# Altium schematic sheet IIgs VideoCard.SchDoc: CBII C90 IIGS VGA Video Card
size A2; Engineer: srkh; DocumentNumber: 1; Revision: c90; SheetNumber: 1; SheetTotal: 1
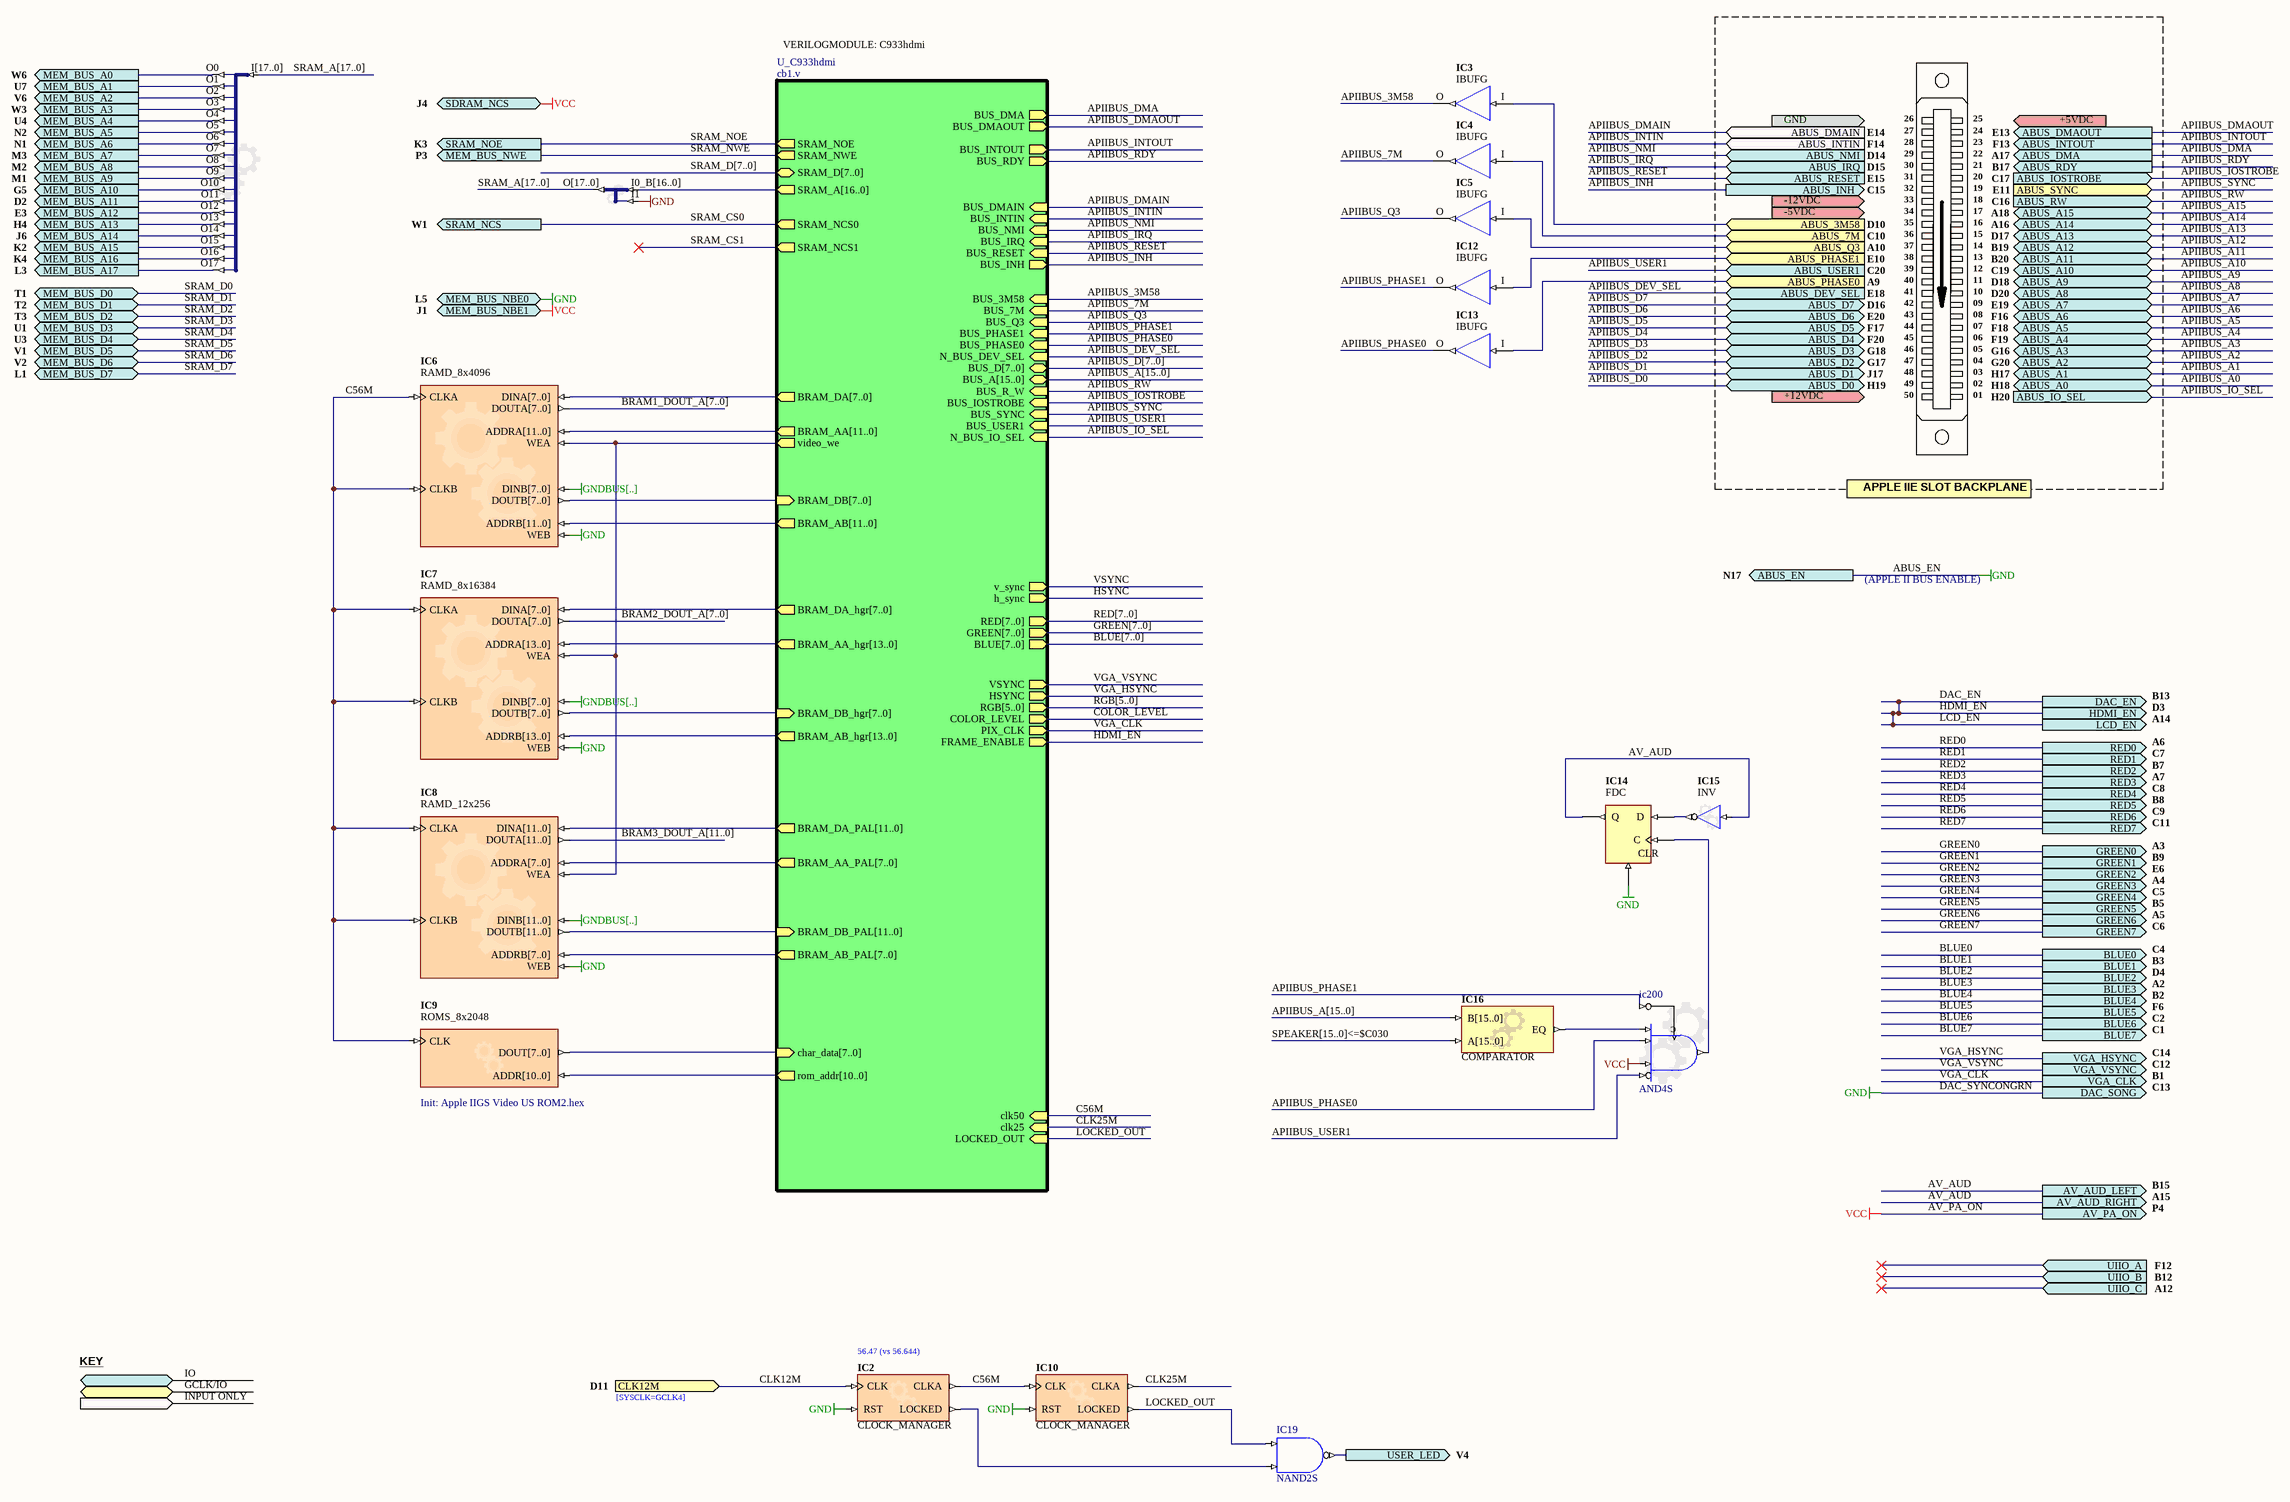
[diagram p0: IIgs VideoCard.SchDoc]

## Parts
IC2  CLOCK_MANAGER
IC3  IBUFG
IC4  IBUFG
IC5  IBUFG
IC6  RAMD_8x4096
IC7  RAMD_8x16384
IC8  RAMD_12x256
IC9  ROMS_8x2048
IC10  CLOCK_MANAGER
IC11  BUS_JS  (value not drawn)
IC12  IBUFG
IC13  IBUFG
IC14  FDC
IC15  INV
IC16  COMPARATOR
IC19  NAND2S
ic200  AND4S
U3001  BUS_JS  (value not drawn)

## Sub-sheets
U_C933hdmi = cb1.v: BLUE[7..0] (out), BUS_3M58 (in), BUS_7M (in), BUS_A[15..0] (bidir), BUS_D[7..0] (bidir), BUS_DMA (out), BUS_DMAIN (in), BUS_DMAOUT (out), BUS_INH (out), BUS_INTIN (in), BUS_INTOUT (out), BUS_IOSTROBE (in), BUS_IRQ (in), BUS_NMI (in), BUS_PHASE0 (in), BUS_PHASE1 (in), BUS_Q3 (in), BUS_R_W (in), BUS_RDY (out), BUS_RESET (in), BUS_SYNC (in), BUS_USER1 (in), COLOR_LEVEL (out), FRAME_ENABLE (out), GREEN[7..0] (out), h_sync (out), HSYNC (out), N_BUS_DEV_SEL (in), N_BUS_IO_SEL (in), PIX_CLK (out), RED[7..0] (out), RGB[5..0] (out), SRAM_A[16..0] (out), SRAM_D[7..0] (bidir), SRAM_NCS0 (out), SRAM_NCS1 (out), SRAM_NOE (out), SRAM_NWE (out), v_sync (out), VSYNC (out), clk25 (in), clk50 (in), LOCKED_OUT (in), rom_addr[10..0] (out), char_data[7..0] (in), BRAM_AA_PAL[7..0] (out), BRAM_DA_PAL[11..0] (out), BRAM_AB_PAL[7..0] (out), BRAM_DB_PAL[11..0] (in), BRAM_AA[11..0] (out), BRAM_DA[7..0] (out), video_we (out), BRAM_AB[11..0] (out), BRAM_DB[7..0] (in), BRAM_AA_hgr[13..0] (out), BRAM_DA_hgr[7..0] (out), BRAM_AB_hgr[13..0] (out), BRAM_DB_hgr[7..0] (in)  | VERILOGMODULE: C933hdmi

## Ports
ABUS_3M58 (in, see D10), ABUS_7M (in, see C10), ABUS_A0 (bidir, see H18), ABUS_A1 (bidir, see H17), ABUS_A2 (bidir, see G20), ABUS_A3 (bidir, see G16), ABUS_A4 (bidir, see F19), ABUS_A5 (bidir, see F18), ABUS_A6 (bidir, see F16), ABUS_A7 (bidir, see E19), ABUS_A8 (bidir, see D20), ABUS_A9 (bidir, see D18), ABUS_A10 (bidir, see C19), ABUS_A11 (bidir, see B20), ABUS_A12 (bidir, see B19), ABUS_A13 (bidir, see D17), ABUS_A14 (bidir, see A16), ABUS_A15 (bidir, see A18), ABUS_D0 (bidir, see H19), ABUS_D1 (bidir, see J17), ABUS_D2 (bidir, see G17), ABUS_D3 (bidir, see G18), ABUS_D4 (bidir, see F20), ABUS_D5 (bidir, see F17), ABUS_D6 (bidir, see E20), ABUS_D7 (bidir, see D16), ABUS_DEV_SEL (in, see E18), ABUS_DMA (out, see A17), ABUS_DMAIN (in, see E14), ABUS_DMAOUT (out, see E13), ABUS_EN (out, see N17), ABUS_INH (out, see C15), ABUS_INTIN (in, see F14), ABUS_INTOUT (out, see F13), ABUS_IO_SEL (in, see H20), ABUS_IOSTROBE (in, see C17), ABUS_IRQ (in, see D15), ABUS_NMI (in, see D14), ABUS_PHASE0 (in, see A9), ABUS_PHASE1 (in, see E10), ABUS_Q3 (in, see A10), ABUS_RDY (out, see B17), ABUS_RESET (in, see E15), ABUS_RW (in, see C16), ABUS_SYNC (in, see E11), ABUS_USER1 (in, see C20), AV_AUD_LEFT (out, see B15), AV_AUD_RIGHT (out, see A15), AV_PA_ON (out, see P4), BLUE0 (out, see C4), BLUE1 (out, see B3), BLUE2 (out, see D4), BLUE3 (out, see A2), BLUE4 (out, see B2), BLUE5 (out, see F6), BLUE6 (out, see C2), BLUE7 (out, see C1), CLK12M (in, see D11), DAC_EN (out, see B13), DAC_SONG (out, see C13), GREEN0 (out, see A3), GREEN1 (out, see B9), GREEN2 (out, see E6), GREEN3 (out, see A4), GREEN4 (out, see C5), GREEN5 (out, see B5), GREEN6 (out, see A5), GREEN7 (out, see C6), HDMI_EN (out, see D3), LCD_EN (out, see A14), MEM_BUS_A0 (out, see W6), MEM_BUS_A1 (out, see U7), MEM_BUS_A2 (out, see V6), MEM_BUS_A3 (out, see W3), MEM_BUS_A4 (out, see U4), MEM_BUS_A5 (out, see N2), MEM_BUS_A6 (out, see N1), MEM_BUS_A7 (out, see M3), MEM_BUS_A8 (out, see M2), MEM_BUS_A9 (out, see M1), MEM_BUS_A10 (out, see G5), MEM_BUS_A11 (out, see D2), MEM_BUS_A12 (out, see E3), MEM_BUS_A13 (out, see H4), MEM_BUS_A14 (out, see J6), MEM_BUS_A15 (out, see K2), MEM_BUS_A16 (out, see K4), MEM_BUS_A17 (out, see L3), MEM_BUS_D0 (bidir, see T1), MEM_BUS_D1 (bidir, see T2), MEM_BUS_D2 (bidir, see T3), MEM_BUS_D3 (bidir, see U1), MEM_BUS_D4 (bidir, see U3), MEM_BUS_D5 (bidir, see V1), MEM_BUS_D6 (bidir, see V2), MEM_BUS_D7 (bidir, see L1), MEM_BUS_NBE0 (out, see L5), MEM_BUS_NBE1 (out, see J1), MEM_BUS_NWE (out, see P3), RED0 (out, see A6), RED1 (out, see C7), RED2 (out, see B7), RED3 (out, see A7), RED4 (out, see C8), RED5 (out, see B8), RED6 (out, see C9), RED7 (out, see C11), SDRAM_NCS (out, see J4), SRAM_NCS (out, see W1), SRAM_NOE (out, see K3), UIIO_A (in, see F12), UIIO_B (in, see B12), UIIO_C (in, see A12), USER_LED (out, see V4), VGA_CLK (out, see B1), VGA_HSYNC (out, see C14), VGA_VSYNC (out, see C12)

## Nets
ABUS_EN: IC2.RST IC6.WEB IC7.WEB IC8.WEB IC10.RST IC14.CLR U3001.I1 ; port ABUS_EN, port DAC_SONG, port MEM_BUS_NBE0  [also labelled DAC_SYNCONGRN, GND]
AV_PA_ON: ic200.I1 ; port AV_PA_ON, port MEM_BUS_NBE1, port SDRAM_NCS  [also labelled VCC]
GNDBUS[..]: IC6.DINB[7..0] IC7.DINB[7..0] IC8.DINB[11..0]
ABUS_3M58: IC3.I ; port ABUS_3M58
ABUS_7M: IC4.I ; port ABUS_7M
ABUS_PHASE0: IC13.I ; port ABUS_PHASE0
ABUS_PHASE1: IC12.I ; port ABUS_PHASE1
ABUS_Q3: IC5.I ; port ABUS_Q3
APIIBUS_3M58: IC3.O ; sheet U_C933hdmi/BUS_3M58
APIIBUS_7M: IC4.O ; sheet U_C933hdmi/BUS_7M
APIIBUS_DEV_SEL: port ABUS_DEV_SEL, sheet U_C933hdmi/N_BUS_DEV_SEL
APIIBUS_DMA: port ABUS_DMA, sheet U_C933hdmi/BUS_DMA
APIIBUS_DMAIN: port ABUS_DMAIN, sheet U_C933hdmi/BUS_DMAIN
APIIBUS_DMAOUT: port ABUS_DMAOUT, sheet U_C933hdmi/BUS_DMAOUT
APIIBUS_INH: port ABUS_INH, sheet U_C933hdmi/BUS_INH
APIIBUS_INTIN: port ABUS_INTIN, sheet U_C933hdmi/BUS_INTIN
APIIBUS_INTOUT: port ABUS_INTOUT, sheet U_C933hdmi/BUS_INTOUT
APIIBUS_IO_SEL: port ABUS_IO_SEL, sheet U_C933hdmi/N_BUS_IO_SEL
APIIBUS_IOSTROBE: port ABUS_IOSTROBE, sheet U_C933hdmi/BUS_IOSTROBE
APIIBUS_IRQ: port ABUS_IRQ, sheet U_C933hdmi/BUS_IRQ
APIIBUS_NMI: port ABUS_NMI, sheet U_C933hdmi/BUS_NMI
APIIBUS_PHASE0: IC13.O ic200.I2 ; sheet U_C933hdmi/BUS_PHASE0
APIIBUS_PHASE1: IC12.O ic200.C ; sheet U_C933hdmi/BUS_PHASE1
APIIBUS_Q3: IC5.O ; sheet U_C933hdmi/BUS_Q3
APIIBUS_RDY: port ABUS_RDY, sheet U_C933hdmi/BUS_RDY
APIIBUS_RESET: port ABUS_RESET, sheet U_C933hdmi/BUS_RESET
APIIBUS_RW: port ABUS_RW, sheet U_C933hdmi/BUS_R_W
APIIBUS_SYNC: port ABUS_SYNC, sheet U_C933hdmi/BUS_SYNC
APIIBUS_USER1: ic200.I0 ; port ABUS_USER1, sheet U_C933hdmi/BUS_USER1
AV_AUD: IC14.Q IC15.I ; port AV_AUD_LEFT, port AV_AUD_RIGHT
C56M: IC2.CLKA IC6.CLKA IC6.CLKB IC7.CLKA IC7.CLKB IC8.CLKA IC8.CLKB IC9.CLK IC10.CLK ; sheet U_C933hdmi/clk50
CLK12M: IC2.CLK ; port CLK12M
CLK25M: IC10.CLKA ; sheet U_C933hdmi/clk25
DAC_EN: port HDMI_EN, port DAC_EN, port LCD_EN, sheet U_C933hdmi/FRAME_ENABLE  [also labelled HDMI_EN, LCD_EN]
LOCKED_OUT: IC10.LOCKED IC19.I1 ; sheet U_C933hdmi/LOCKED_OUT
MEM_BUS_A0: IC11.O0 ; port MEM_BUS_A0
MEM_BUS_A1: IC11.O1 ; port MEM_BUS_A1
MEM_BUS_A2: IC11.O2 ; port MEM_BUS_A2
MEM_BUS_A3: IC11.O3 ; port MEM_BUS_A3
MEM_BUS_A4: IC11.O4 ; port MEM_BUS_A4
MEM_BUS_A5: IC11.O5 ; port MEM_BUS_A5
MEM_BUS_A6: IC11.O6 ; port MEM_BUS_A6
MEM_BUS_A7: IC11.O7 ; port MEM_BUS_A7
MEM_BUS_A8: IC11.O8 ; port MEM_BUS_A8
MEM_BUS_A9: IC11.O9 ; port MEM_BUS_A9
MEM_BUS_A10: IC11.O10 ; port MEM_BUS_A10
MEM_BUS_A11: IC11.O11 ; port MEM_BUS_A11
MEM_BUS_A12: IC11.O12 ; port MEM_BUS_A12
MEM_BUS_A13: IC11.O13 ; port MEM_BUS_A13
MEM_BUS_A14: IC11.O14 ; port MEM_BUS_A14
MEM_BUS_A15: IC11.O15 ; port MEM_BUS_A15
MEM_BUS_A16: IC11.O16 ; port MEM_BUS_A16
MEM_BUS_A17: IC11.O17 ; port MEM_BUS_A17
SRAM_CS0: port SRAM_NCS, sheet U_C933hdmi/SRAM_NCS0
SRAM_NOE: port SRAM_NOE, sheet U_C933hdmi/SRAM_NOE
SRAM_NWE: port MEM_BUS_NWE, sheet U_C933hdmi/SRAM_NWE
USER_LED: IC19.O ; port USER_LED
VGA_CLK: port VGA_CLK, sheet U_C933hdmi/PIX_CLK
VGA_HSYNC: port VGA_HSYNC, sheet U_C933hdmi/HSYNC
VGA_VSYNC: port VGA_VSYNC, sheet U_C933hdmi/VSYNC
NetIC2_LOCKED: IC2.LOCKED IC19.I0
NetIC6_WEA: IC6.WEA IC7.WEA IC8.WEA ; sheet U_C933hdmi/video_we
NetIC14_C: IC14.C ic200.O
NetIC14_D: IC14.D IC15.O
NetIC16_EQ: IC16.EQ ic200.I3

Not connected (* = marked no-connect by the designer): IC6 ADDRA[11..0] ADDRB[11..0] DINA[7..0] DOUTA[7..0] DOUTB[7..0]; IC7 ADDRA[13..0] ADDRB[13..0] DINA[7..0] DOUTA[7..0] DOUTB[7..0]; IC8 ADDRA[7..0] ADDRB[7..0] DINA[11..0] DOUTA[11..0] DOUTB[11..0]; IC9 ADDR[10..0] DOUT[7..0]; IC11 I[17..0]; IC16 A[15..0] B[15..0]; U3001 I0_B[16..0] O[17..0]

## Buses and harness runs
bus APIIBUS_A[15..0]
bus APIIBUS_A[15..0] = sheet U_C933hdmi/BUS_A[15..0]
bus APIIBUS_D[7..0] = sheet U_C933hdmi/BUS_D[7..0]
bus BLUE[7..0] = sheet U_C933hdmi/BLUE[7..0]
bus BRAM1_DOUT_A[7..0]
bus BRAM2_DOUT_A[7..0]
bus BRAM3_DOUT_A[11..0]
bus GREEN[7..0] = sheet U_C933hdmi/GREEN[7..0]
bus RED[7..0] = sheet U_C933hdmi/RED[7..0]
bus RGB[5..0] = sheet U_C933hdmi/RGB[5..0]
bus SPEAKER[15..0]<=$C030
bus SRAM_A[17..0]
bus SRAM_D[7..0] = sheet U_C933hdmi/SRAM_D[7..0]

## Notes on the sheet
- GND
- 26
- 25
- +5VDC
- 27
- 28
- 29
- 30
- 31
- 24
- 23
- 22
- 21
- 20
- -12VDC
- -5VDC
- 32
- 33
- 34
- 35
- 36
- 19
- 18
- 17
- 16
- 15
- 37
- 38
- 39
- 40
- 41
- 14
- 13
- 12
- 11
- 10
- 42
- 43
- 44
- 45
- 46
- 09
- 08
- 07
- 06
- 05
- +12VDC
- 47
- 48
- 49
- 50
- 04
- 03
- 02
- 01
- APPLE IIE SLOT BACKPLANE
- (APPLE II BUS ENABLE)
- KEY
- IO
- GCLK/IO
- (near IC2) 56.47 (vs 56.644)
- INPUT ONLY
- [SYSCLK=GCLK4]

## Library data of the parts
IC2 = CLOCKMANAGER: Configurable Clock Manager; ConfiguratorName: GENERIC_CLOCKMANAGER; ConfigurationParameters: {}Version[1.0]{}Option_Configuration[object _1: TClockManagerPersist / VersionMajor [ 0 / VersionMinor [ 0 / InputFreq [ 24.000000000000000000 / InputName [ 'CLK' / OutputTargets [ < / item / Name [ 'CLKA' / OutFreqMin [ 111.810600000000000000 / OutFreqMax [ 114.069400000000000000 / OutPostDivider [ 1.000000000000000000 / end> / OutputDevices [ < / item / Name [ 'Spartan3E' / Valid [ True / OutputActuals [ < / item / Name [ 'CLK0' / Multipler [ 1.000000000000000000 / Divider [ 1.000000000000000000 / OutFreq [ 120.000000000000000000 / OutputMap [ 1 / end / item / Name [ 'CLK90' / Multipler [ 1.000000000000000000 / Divider [ 1.000000000000000000 / OutPhase [ 90.000000000000000000 / OutFreq [ 120.000000000000000000 / OutputMap [ 2 / end / item / Name [ 'CLK180' / Multipler [ 1.000000000000000000 / Divider [ 1.000000000000000000 / OutPhase [ 180.000000000000000000 / OutFreq [ 120.000000000000000000 / OutputMap [ 3 / end / item / Name [ 'CLK270' / Multipler [ 1.000000000000000000 / Divider [ 1.000000000000000000 / OutPhase [ 270.000000000000000000 / OutFreq [ 120.000000000000000000 / OutputMap [ 4 / end / item / Name [ 'CLK2X' / Multipler [ 2.000000000000000000 / Divider [ 1.000000000000000000 / OutFreq [ 240.000000000000000000 / OutputMap [ 5 / end / item / Name [ 'CLKDV' / Multipler [ 1.000000000000000000 / Divider [ 16.000000000000000000 / OutFreq [ 7.500000000000000000 / OutputMap [ 6 / end / item / Name [ 'CLK2X180' / Multipler [ 1.000000000000000000 / Divider [ 1.000000000000000000 / OutPhase [ 180.000000000000000000 / OutFreq [ 240.000000000000000000 / OutputMap [ 7 / end / item / Name [ 'CLKFX' / Multipler [ 5.000000000000000000 / Divider [ 12.000000000000000000 / OutFreq [ 50.000000000000000000 / OutputMap [ 0 / end / item / Name [ 'CLKFX180' / Multipler [ 1.000000000000000000 / Divider [ 1.000000000000000000 / OutPhase [ 180.000000000000000000 / OutFreq [ 50.000000000000000000 / OutputMap [ 8 / end> / InternalActuals [ <> / CustomVars [ <> / end / item / Name [ 'Spartan3AN' / Valid [ True / OutputActuals [ < / item / Name [ 'CLK0' / Multipler [ 1.000000000000000000 / Divider [ 1.000000000000000000 / OutFreq [ 24.000000000000000000 / OutputMap [ 1 / end / item / Name [ 'CLK90' / Multipler [ 1.000000000000000000 / Divider [ 1.000000000000000000 / OutPhase [ 90.000000000000000000 / OutFreq [ 24.000000000000000000 / OutputMap [ 2 / end / item / Name [ 'CLK180' / Multipler [ 1.000000000000000000 / Divider [ 1.000000000000000000 / OutPhase [ 180.000000000000000000 / OutFreq [ 24.000000000000000000 / OutputMap [ 3 / end / item / Name [ 'CLK270' / Multipler [ 1.000000000000000000 / Divider [ 1.000000000000000000 / OutPhase [ 270.000000000000000000 / OutFreq [ 24.000000000000000000 / OutputMap [ 4 / end / item / Name [ 'CLK2X' / Multipler [ 2.000000000000000000 / Divider [ 1.000000000000000000 / OutFreq [ 48.000000000000000000 / OutputMap [ 5 / end / item / Name [ 'CLKDV' / Multipler [ 1.000000000000000000 / Divider [ 16.000000000000000000 / OutFreq [ 1.500000000000000000 / OutputMap [ 6 / end / item / Name [ 'CLK2X180' / Multipler [ 1.000000000000000000 / Divider [ 1.000000000000000000 / OutPhase [ 180.000000000000000000 / OutFreq [ 48.000000000000000000 / OutputMap [ 7 / end / item / Name [ 'CLKFX' / Multipler [ 14.000000000000000000 / Divider [ 3.000000000000000000 / OutFreq [ 112.000000000000000000 / OutputMap [ 0 / end / item / Name [ 'CLKFX180' / Multipler [ 1.000000000000000000 / Divider [ 1.000000000000000000 / OutPhase [ 180.000000000000000000 / OutFreq [ 112.000000000000000000 / OutputMap [ 8 / end> / InternalActuals [ <> / CustomVars [ <> / end> / MinInputFreq [ 1.000000000000000000 / MaxInputFreq [ 280.000000000000000000 / MinOutputFreq [ 18.000000000000000000 / MaxOutputFreq [ 210.000000000000000000 / MaxOutputCount [ 9 / end]{}
IC3 IC4 IC12 IC13 = IBUFG: Dedicated Input Buffer using the LVTTL standard; FPGAVendor: Xilinx
IC5 = IBUF: Single-Input Buffer; FPGAVendor: Xilinx
IC6 = MEMORY: Configurable Memory; ConfiguratorName: GENERIC_MEMORY; ConfigurationParameters: {}Version[1.0]{}Option_MemoryDepthText[4096]{}Option_MemoryWidth[8]{}Option_PortCount[1]{}Option_MemoryType[0]{}Option_ByteWrites[False]{}Option_RisingEdgeClock[True]{}Option_EnablePin[False]{}Option_ResetPin[False]{}Option_UseDistributed[False]{}Option_InitMemoryFlag[False]{}Option_MemoryFileName[ ]{}Option_MemoryFileEndiannessBig[False]{}Option_MemoryFileEndiannessLittle[True]{}
IC7 = MEMORY: Configurable Memory; ConfiguratorName: GENERIC_MEMORY; ConfigurationParameters: {}Version[1.0]{}Option_MemoryDepthText[16384]{}Option_MemoryWidth[8]{}Option_PortCount[1]{}Option_MemoryType[0]{}Option_ByteWrites[False]{}Option_RisingEdgeClock[True]{}Option_EnablePin[False]{}Option_ResetPin[False]{}Option_UseDistributed[False]{}Option_InitMemoryFlag[False]{}Option_MemoryFileName[ ]{}Option_MemoryFileEndiannessBig[False]{}Option_MemoryFileEndiannessLittle[True]{}
IC8 = MEMORY: Configurable Memory; ConfiguratorName: GENERIC_MEMORY; ConfigurationParameters: {}Version[1.0]{}Option_MemoryDepthText[256]{}Option_MemoryWidth[12]{}Option_PortCount[1]{}Option_MemoryType[0]{}Option_ByteWrites[False]{}Option_RisingEdgeClock[True]{}Option_EnablePin[False]{}Option_ResetPin[False]{}Option_UseDistributed[False]{}Option_InitMemoryFlag[False]{}Option_MemoryFileName[ ]{}Option_MemoryFileEndiannessBig[False]{}Option_MemoryFileEndiannessLittle[True]{}
IC9 = MEMORY: Configurable Memory; ConfiguratorName: GENERIC_MEMORY; ConfigurationParameters: {}Version[1.0]{}Option_MemoryDepthText[2048]{}Option_MemoryWidth[8]{}Option_PortCount[0]{}Option_MemoryType[1]{}Option_ByteWrites[False]{}Option_RisingEdgeClock[True]{}Option_EnablePin[False]{}Option_ResetPin[False]{}Option_UseDistributed[False]{}Option_InitMemoryFlag[True]{}Option_MemoryFileName[C:\Designs_250114\SRKH\Carte Blanche DVI card\Charlie _AD Version\Apple IIGS Video US ROM2.hex]{}Option_MemoryFileEndiannessBig[True]{}Option_MemoryFileEndiannessLittle[False]{}
IC10 = CLOCKMANAGER: Configurable Clock Manager; ConfiguratorName: GENERIC_CLOCKMANAGER; ConfigurationParameters: {}Version[1.0]{}Option_Configuration[object _1: TClockManagerPersist / VersionMajor [ 0 / VersionMinor [ 0 / InputFreq [ 50.000000000000000000 / InputName [ 'CLK' / OutputTargets [ < / item / Name [ 'CLKA' / OutFreqMin [ 24.750000000000000000 / OutFreqMax [ 25.250000000000000000 / OutPostDivider [ 1.000000000000000000 / end> / OutputDevices [ < / item / Name [ 'Spartan3E' / Valid [ True / OutputActuals [ < / item / Name [ 'CLK0' / Multipler [ 1.000000000000000000 / Divider [ 1.000000000000000000 / OutFreq [ 14.318180000000000000 / OutputMap [ 1 / end / item / Name [ 'CLK90' / Multipler [ 1.000000000000000000 / Divider [ 1.000000000000000000 / OutPhase [ 90.000000000000000000 / OutFreq [ 14.318180000000000000 / OutputMap [ 2 / end / item / Name [ 'CLK180' / Multipler [ 1.000000000000000000 / Divider [ 1.000000000000000000 / OutPhase [ 180.000000000000000000 / OutFreq [ 14.318180000000000000 / OutputMap [ 3 / end / item / Name [ 'CLK270' / Multipler [ 1.000000000000000000 / Divider [ 1.000000000000000000 / OutPhase [ 270.000000000000000000 / OutFreq [ 14.318180000000000000 / OutputMap [ 4 / end / item / Name [ 'CLK2X' / Multipler [ 2.000000000000000000 / Divider [ 1.000000000000000000 / OutFreq [ 28.636360000000000000 / OutputMap [ 5 / end / item / Name [ 'CLKDV' / Multipler [ 1.000000000000000000 / Divider [ 16.000000000000000000 / OutFreq [ 0.894886250000000000 / OutputMap [ 6 / end / item / Name [ 'CLK2X180' / Multipler [ 1.000000000000000000 / Divider [ 1.000000000000000000 / OutPhase [ 180.000000000000000000 / OutFreq [ 28.636360000000000000 / OutputMap [ 7 / end / item / Name [ 'CLKFX' / Multipler [ 7.000000000000000000 / Divider [ 4.000000000000000000 / OutFreq [ 25.056815000000000000 / OutputMap [ 0 / end / item / Name [ 'CLKFX180' / Multipler [ 1.000000000000000000 / Divider [ 1.000000000000000000 / OutPhase [ 180.000000000000000000 / OutFreq [ 25.056815000000000000 / OutputMap [ 8 / end> / InternalActuals [ <> / CustomVars [ <> / end / item / Name [ 'Spartan3AN' / Valid [ True / OutputActuals [ < / item / Name [ 'CLK0' / Multipler [ 1.000000000000000000 / Divider [ 1.000000000000000000 / OutFreq [ 50.000000000000000000 / OutputMap [ 1 / end / item / Name [ 'CLK90' / Multipler [ 1.000000000000000000 / Divider [ 1.000000000000000000 / OutPhase [ 90.000000000000000000 / OutFreq [ 50.000000000000000000 / OutputMap [ 2 / end / item / Name [ 'CLK180' / Multipler [ 1.000000000000000000 / Divider [ 1.000000000000000000 / OutPhase [ 180.000000000000000000 / OutFreq [ 50.000000000000000000 / OutputMap [ 3 / end / item / Name [ 'CLK270' / Multipler [ 1.000000000000000000 / Divider [ 1.000000000000000000 / OutPhase [ 270.000000000000000000 / OutFreq [ 50.000000000000000000 / OutputMap [ 4 / end / item / Name [ 'CLK2X' / Multipler [ 2.000000000000000000 / Divider [ 1.000000000000000000 / OutFreq [ 100.000000000000000000 / OutputMap [ 5 / end / item / Name [ 'CLKDV' / Multipler [ 1.000000000000000000 / Divider [ 2.000000000000000000 / OutFreq [ 25.000000000000000000 / OutputMap [ 0 / end / item / Name [ 'CLK2X180' / Multipler [ 1.000000000000000000 / Divider [ 1.000000000000000000 / OutPhase [ 180.000000000000000000 / OutFreq [ 100.000000000000000000 / OutputMap [ 6 / end / item / Name [ 'CLKFX' / Multipler [ 2.000000000000000000 / Divider [ 1.000000000000000000 / OutFreq [ 100.000000000000000000 / OutputMap [ 7 / end / item / Name [ 'CLKFX180' / Multipler [ 1.000000000000000000 / Divider [ 1.000000000000000000 / OutPhase [ 180.000000000000000000 / OutFreq [ 100.000000000000000000 / OutputMap [ 8 / end> / InternalActuals [ <> / CustomVars [ <> / end> / MinInputFreq [ 1.000000000000000000 / MaxInputFreq [ 280.000000000000000000 / MinOutputFreq [ 18.000000000000000000 / MaxOutputFreq [ 210.000000000000000000 / MaxOutputCount [ 9 / end]{}
IC11 = BUS_JS: Configurable Bus Joiner/Splitter; ConfiguratorName: GENERIC_BUS_JS; ConfigurationParameters: {}Version[1.1]{}SplitterJoinerType[Splitter]{}SignalCount[18]{}SignalWidth0[1]{}GapBelow0[1000000]{}ConnectionType0[Pin]{}SignalWidth1[1]{}GapBelow1[1000000]{}ConnectionType1[Pin]{}SignalWidth2[1]{}GapBelow2[1000000]{}ConnectionType2[Pin]{}SignalWidth3[1]{}GapBelow3[1000000]{}ConnectionType3[Pin]{}SignalWidth4[1]{}GapBelow4[1000000]{}ConnectionType4[Pin]{}SignalWidth5[1]{}GapBelow5[1000000]{}ConnectionType5[Pin]{}SignalWidth6[1]{}GapBelow6[1000000]{}ConnectionType6[Pin]{}SignalWidth7[1]{}GapBelow7[1000000]{}ConnectionType7[Pin]{}SignalWidth8[1]{}GapBelow8[1000000]{}ConnectionType8[Pin]{}SignalWidth9[1]{}GapBelow9[1000000]{}ConnectionType9[Pin]{}SignalWidth10[1]{}GapBelow10[1000000]{}ConnectionType10[Pin]{}SignalWidth11[1]{}GapBelow11[1000000]{}ConnectionType11[Pin]{}SignalWidth12[1]{}GapBelow12[1000000]{}ConnectionType12[Pin]{}SignalWidth13[1]{}GapBelow13[1000000]{}ConnectionType13[Pin]{}SignalWidth14[1]{}GapBelow14[1000000]{}ConnectionType14[Pin]{}SignalWidth15[1]{}GapBelow15[1000000]{}ConnectionType15[Pin]{}SignalWidth16[1]{}GapBelow16[1000000]{}ConnectionType16[Pin]{}SignalWidth17[1]{}GapBelow17[1000000]{}ConnectionType17[Pin]{}ShowPinNames[True]{}
IC14 = FDC: D Flip-Flop with Asynchronous Clear; FPGAVendor: Xilinx
IC15 = INV: Configurable Inverter; ConfiguratorName: GENERIC_BUFFER; ConfigurationParameters: {}Version[1.1]{}SignalCount[1]{}SignalWidth0[1]{}OutputOption0[Inverted]{}EnableMode[None]{}ShowPinNames[False]{}
IC16 = COMPARATOR: Configurable Comparator; ConfiguratorName: GENERIC_COMPARATOR; ConfigurationParameters: {}Version[1.0]{}EQ[True]{}GT[False]{}LT[False]{}SignalWidth[16]{}BusInputs[True]{}RegisterOutputs[False]{}NegClockEdge[False]{}
IC19 = NAND2: 2-Input NAND Gate, Single Pin Version; ArchiveName: GENERIC; XilinxEquivalent: NAND2; FunctionalClass: Logic Primitive; PortSize: 2; VHDLIB_SIM: GENERIC_LIB
ic200 = GATE: Configurable Generic Gate; ConfiguratorName: GENERIC_GATE; ConfigurationParameters: {}Version[1.1]{}GateKind[AND]{}BusInput[False]{}GateInputType[Bit]{}GateOutputOption[Normal]{}BusWidth[8]{}RegisterOutputs[True]{}NegativeClockEdge[True]{}InputCount[4]{}InputInvert0[True]{}InputInvert1[False]{}InputInvert2[False]{}InputInvert3[False]{}
U3001 = BUS_JS: Configurable Bus Joiner/Splitter; ConfiguratorName: GENERIC_BUS_JS; ConfigurationParameters: {}Version[1.1]{}SplitterJoinerType[Joiner]{}SignalCount[2]{}SignalWidth0[17]{}GapBelow0[1000000]{}ConnectionType0[Pin]{}SignalWidth1[1]{}GapBelow1[1000000]{}ConnectionType1[Pin]{}ShowPinNames[True]{}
